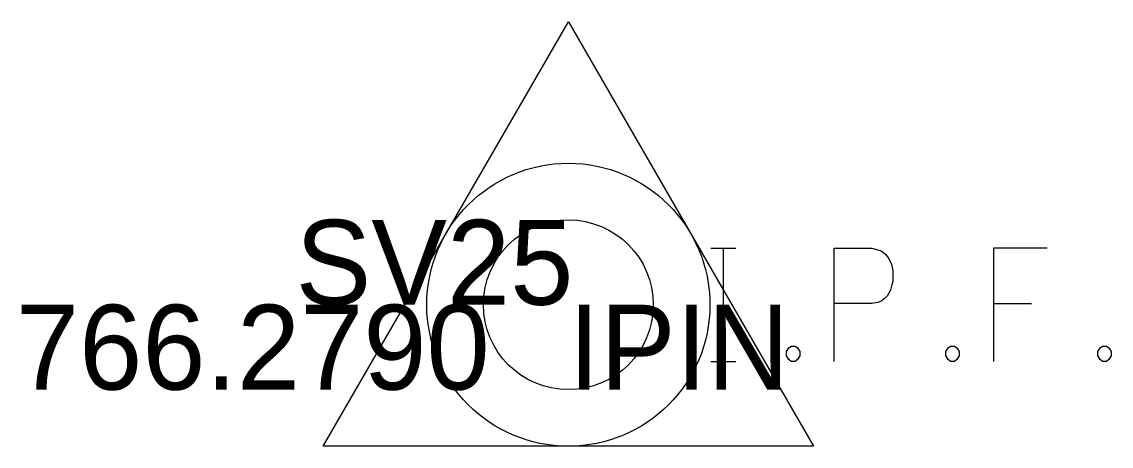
# Model space of a CAD drawing. Extents: x 1857337 to 1857837, y 693958 to 694371.
# Drawn here: x 1857527.65 to 1857535.35, y 694342.1 to 694345.1 of the extents above; entities that cross this region are included whole.
import ezdxf

# ---------------------------------------------------------------- set-up
doc = ezdxf.new("R2010")
doc.units = 0
for name, color, linetype in [('DR_X_Cells', 7, 'Continuous'), ('GK_Drainage_Nodes', 7, 'Continuous'), ('SV_X_Text_Comment', 7, 'Continuous'), ('SV_X_Text_Description', 7, 'Continuous'), ('SV_X_Text_Name', 7, 'Continuous')]:
    doc.layers.add(name, color=color, linetype=linetype)

msp = doc.modelspace()

# ---------------------------------------------------------------- linework, layer by layer
at = {"layer": 'DR_X_Cells'}
for points in [[(1857532.5192, 694343.496), (1857532.6956, 694343.496)], [(1857532.6074, 694342.696), (1857532.6074, 694343.496)], [(1857533.39, 694342.696), (1857533.39, 694343.496), (1857533.6546, 694343.496), (1857533.6822, 694343.4897), (1857533.7207, 694343.4771), (1857533.7373, 694343.4645), (1857533.7538, 694343.4519), (1857533.7758, 694343.4204), (1857533.7924, 694343.3889), (1857533.8034, 694343.3385), (1857533.8034, 694343.2629), (1857533.7979, 694343.2377), (1857533.7868, 694343.1999), (1857533.7648, 694343.1559), (1857533.7427, 694343.1369), (1857533.7262, 694343.1243), (1857533.6986, 694343.1117), (1857533.6546, 694343.1055), (1857533.39, 694343.1055)], [(1857534.8947, 694343.496), (1857534.5143, 694343.496), (1857534.5143, 694342.696)], [(1857534.5143, 694343.1055), (1857534.7844, 694343.1055)], [(1857533.0869, 694342.8031), (1857533.1144, 694342.8031), (1857533.131, 694342.7905), (1857533.1475, 694342.7653), (1857533.1475, 694342.7338), (1857533.131, 694342.7086), (1857533.1144, 694342.696), (1857533.0869, 694342.696), (1857533.0703, 694342.7086), (1857533.0538, 694342.7338), (1857533.0538, 694342.7653), (1857533.0703, 694342.7905), (1857533.0869, 694342.8031)], [(1857534.2113, 694342.8031), (1857534.2388, 694342.8031), (1857534.2553, 694342.7905), (1857534.2718, 694342.7653), (1857534.2718, 694342.7338), (1857534.2553, 694342.7086), (1857534.2388, 694342.696), (1857534.2113, 694342.696), (1857534.1947, 694342.7086), (1857534.1782, 694342.7338), (1857534.1782, 694342.7653), (1857534.1947, 694342.7905), (1857534.2113, 694342.8031)], [(1857535.2859, 694342.8031), (1857535.3135, 694342.8031), (1857535.33, 694342.7905), (1857535.3465, 694342.7653), (1857535.3465, 694342.7338), (1857535.33, 694342.7086), (1857535.3135, 694342.696), (1857535.2859, 694342.696), (1857535.2694, 694342.7086), (1857535.2529, 694342.7338), (1857535.2529, 694342.7653), (1857535.2694, 694342.7905), (1857535.2859, 694342.8031)], [(1857532.5192, 694342.696), (1857532.6956, 694342.696)]]:
    msp.add_lwpolyline(points, dxfattribs=at)
msp.add_circle((1857531.512, 694343.096), 0.6, dxfattribs=at)
at = {"layer": 'GK_Drainage_Nodes'}
for p, q in [((1857529.7799, 694342.096), (1857531.512, 694345.096)), ((1857531.512, 694345.096), (1857533.2441, 694342.096)), ((1857531.512, 694343.096), (1857531.512, 694343.096)), ((1857533.2441, 694342.096), (1857529.7799, 694342.096))]:
    msp.add_line(p, q, dxfattribs=at)
msp.add_circle((1857531.512, 694343.096), 1, dxfattribs=at)

# ---------------------------------------------------------------- texts
at = {"layer": 'SV_X_Text_Comment'}
msp.add_text('IPIN', height=0.6, dxfattribs=at).set_placement((1857531.512, 694342.496))
at = {"layer": 'SV_X_Text_Description'}
msp.add_text('766.2790', height=0.6, dxfattribs=at).set_placement((1857527.6099, 694342.496))
at = {"layer": 'SV_X_Text_Name'}
msp.add_text('SV25', height=0.6, dxfattribs=at).set_placement((1857529.5846, 694343.096))

doc.saveas('drawing.dxf')
